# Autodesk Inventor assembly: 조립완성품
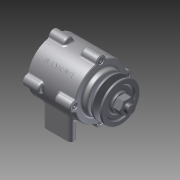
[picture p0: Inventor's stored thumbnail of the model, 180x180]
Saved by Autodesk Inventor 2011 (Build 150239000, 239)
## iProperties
Created: 2015-03
Part Number: 조립완성품
Document SubType Name: Assembly
Designer: Administrator
Author: Administrator
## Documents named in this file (11)
- C:\Documents and Settings\Administrator\바탕 화면\450305V1053\조립완성품.iam
- C:\Documents and Settings\Administrator\바탕 화면\450305V1053\본체.ipt
- C:\Documents and Settings\Administrator\바탕 화면\450305V1053\베어링 6204.ipt
- C:\Documents and Settings\Administrator\바탕 화면\450305V1053\축.ipt
- C:\Documents and Settings\Administrator\바탕 화면\450305V1053\커버2.ipt
- C:\Documents and Settings\Administrator\바탕 화면\450305V1053\커버.ipt
- C:\Documents and Settings\Administrator\바탕 화면\450305V1053\오일실.ipt
- C:\Documents and Settings\Administrator\바탕 화면\450305V1053\키(4 x 4 x 12).ipt
- C:\Documents and Settings\Administrator\바탕 화면\450305V1053\V벨트풀리.ipt
- C:\Documents and Settings\Administrator\바탕 화면\450305V1053\너트 M12x1.25.ipt
- C:\Documents and Settings\Administrator\바탕 화면\450305V1053\M 4 x 12.ipt
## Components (14 placed, 6 different names)
1. KS B 2023 6204 - 20 x 47 x 14:1
2. KS B 2023 6204 - 20 x 47 x 14:2
3. KS B 2804 D D - 20 32 8:1
4. 그루브 풀리1:1 — 각도:7
5. KS B 1012 클래스 1 일반 - 미터 M12x1.25:1 — 각도:9
6. KS B 1311 (I) 4 x 4 x 12:1 — 각도:6, 각도:7, 각도:9
7. KS B 1003 - 미터 M 4 x 12:1 — 각도:4
8. KS B 1003 - 미터 M 4 x 12:2
9. KS B 1003 - 미터 M 4 x 12:3
10. KS B 1003 - 미터 M 4 x 12:4
11. KS B 1003 - 미터 M 4 x 12:5 — 각도:5
12. KS B 1003 - 미터 M 4 x 12:6
13. KS B 1003 - 미터 M 4 x 12:7
14. KS B 1003 - 미터 M 4 x 12:8
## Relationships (5: Angle 5)
- 각도:4 [Angle]: KS B 1003 - 미터 M 4 x 12:1
- 각도:5 [Angle]: KS B 1003 - 미터 M 4 x 12:5
- 각도:6 [Angle]: KS B 1311 (I) 4 x 4 x 12:1
- 각도:7 [Angle]: 그루브 풀리1:1 ↔ KS B 1311 (I) 4 x 4 x 12:1
- 각도:9 [Angle]: KS B 1012 클래스 1 일반 - 미터 M12x1.25:1 ↔ KS B 1311 (I) 4 x 4 x 12:1
